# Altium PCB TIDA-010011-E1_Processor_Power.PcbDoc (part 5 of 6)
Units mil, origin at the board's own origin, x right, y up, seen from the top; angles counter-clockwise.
Board outline 4921.26 x 4921.26 mil, 4 copper layers (Top Layer, Gnd layer, Gnd/Pwr layer, Bottom Layer), stack 62.634 mil thick; 631 components, 254 nets, 1751 pads, 757 vias.
Unrouted connection lines stored in the file: 1.
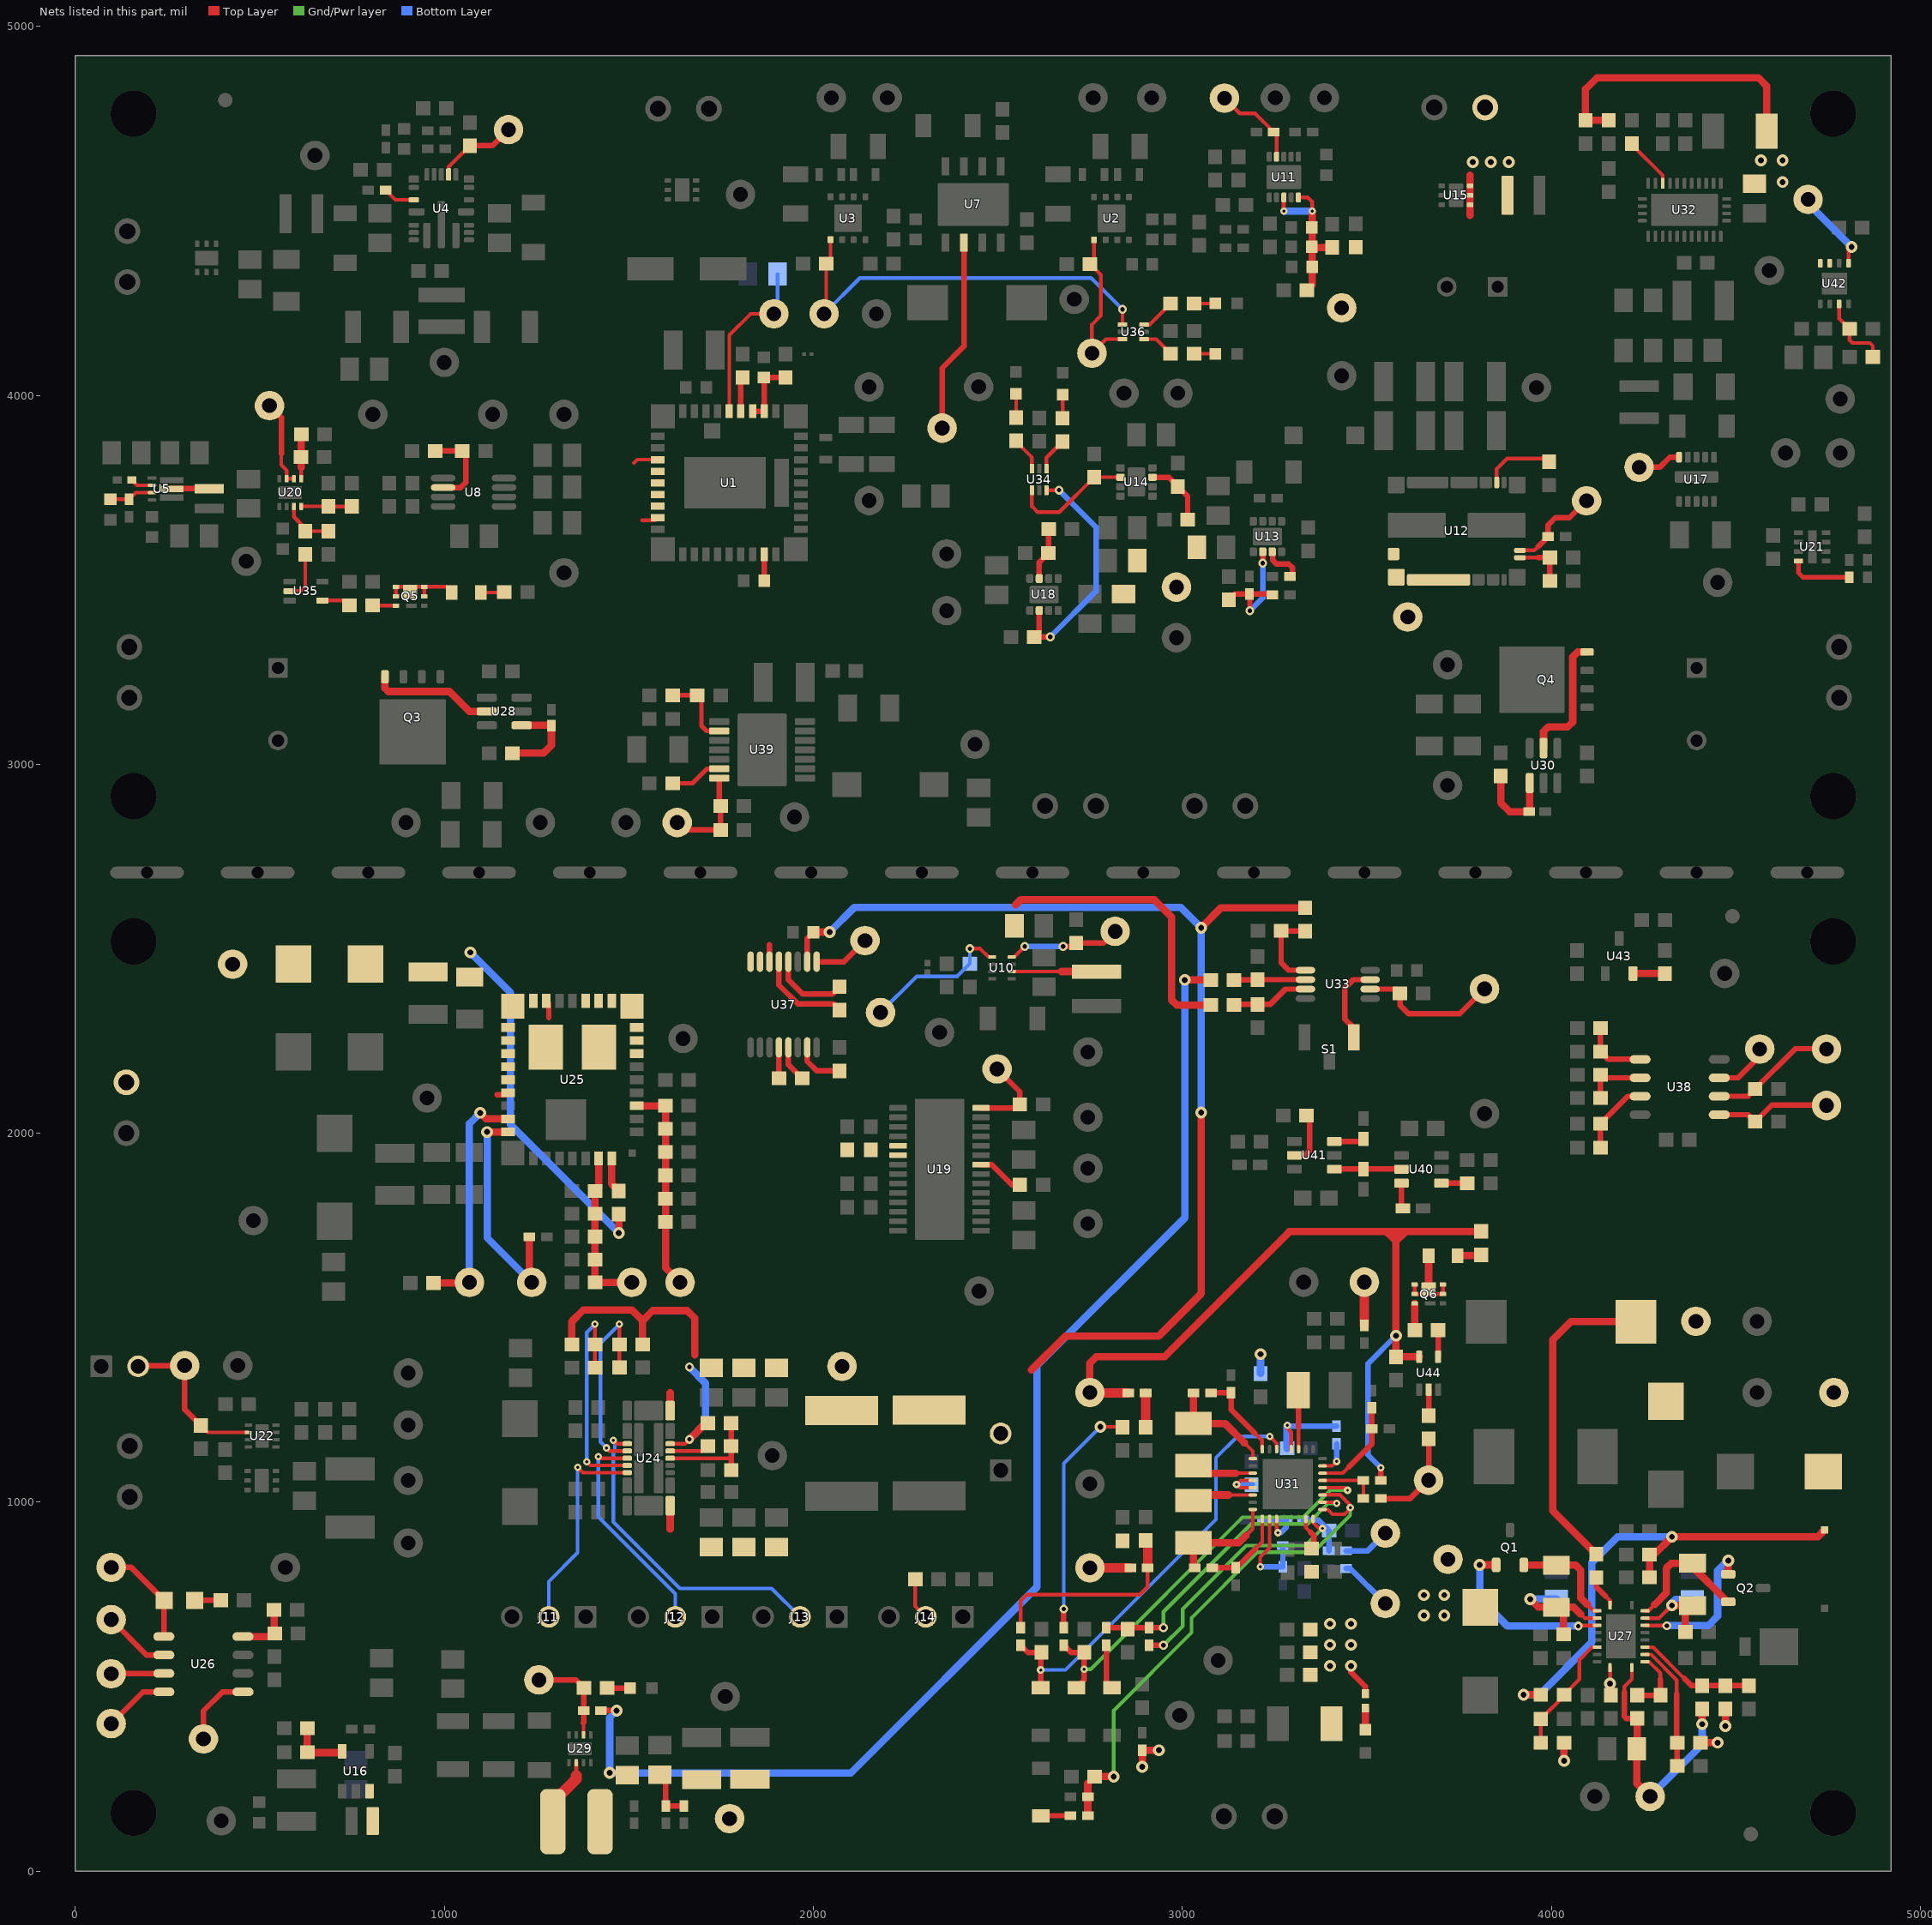
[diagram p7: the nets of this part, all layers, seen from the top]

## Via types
v1: diameter 32, hole 16, Top Layer to Bottom Layer, tented both sides, 400 vias
v2: diameter 19.68, hole 7.87, Top Layer to Bottom Layer, 176 vias
v3: diameter 24, hole 12, Top Layer to Bottom Layer, tented both sides, 112 vias
v4: diameter 20, hole 8, Top Layer to Bottom Layer, tented both sides, 35 vias
v5: diameter 17.72, hole 7.87, Top Layer to Bottom Layer, 30 vias
v6: diameter 19.68, hole 7.87, Top Layer to Bottom Layer, tented both sides, 4 vias

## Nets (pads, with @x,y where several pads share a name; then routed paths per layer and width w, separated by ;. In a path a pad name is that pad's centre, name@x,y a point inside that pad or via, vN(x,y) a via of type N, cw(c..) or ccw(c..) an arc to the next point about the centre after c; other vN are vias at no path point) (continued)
NetD3_1: D3.1 R110.2 U28.1 | length 248.8
  Top Layer w20: R110.2@1184.5,3030 1269,3030 1290,3051 D3.1@1290,3104.35 1288.75,3105.6 U28.1@1209.24,3105.6
NetD4_1: D4.1 R115.2 U30.1 | length 238
  Top Layer w20: R115.2@3863,2967.93 3863,2895.53 3887.1,2871.43 D4.1@3940.35,2871.43 3941.6,2872.68 U30.1@3941.6,2949.18
NetD5_1: D5.1 R120.1 | length 70.6
  Top Layer w15: D5.1@323.15,733.48 392.98,733.48 R120.1@393.5,734
NetD5_2: D5.2 TP63.1 U26.5 | length 279.1
  Top Layer w15: TP63.1@96.81,823 150.95,823 D5.2@240.47,733.48 239.53,732.54 U26.5@239.53,635.48
NetD6_1: D6.1 R132.2 | length 64
  Top Layer w10: R132.2@2549.54,3939.91 D6.1@2549.54,4003.88
NetD7_1: D7.1 R133.2 | length 64
  Top Layer w10: R133.2@2675.54,3937.91 D7.1@2675.54,4001.88
NetD8_1: D8.1 R134.2 | length 62
  Top Layer w15: R134.2@1441.5,496 D8.1@1503.47,496
NetD9_1: D9.1 Q5.1 Q5.2 Q5.5 Q5.6 Q5.8 | length 213.5
  Top Layer w10: Q5.2@868.61,3455.26 Q5.1@868.61,3480.85 894.2,3480.85 900.03,3475.03 905.85,3480.85 Q5.6@945.39,3480.85 ; Q5.5@945.39,3455.26 Q5.6@945.39,3480.85 ; D9.1@1019.63,3465.26 1004.04,3480.85 Q5.6@945.39,3480.85
NetD9_2: D9.2 R135.1 | length 64.5
  Top Layer w10: D9.2@1098.37,3465.26 1161.5,3465.26 R135.1@1162.5,3466.26
NetD10_1: D10.1 R140.2 | length 58.4
  Top Layer w10: R140.2@3031.5,4112.72 3088.47,4112.72 D10.1@3089.47,4111.72
NetD11_1: D11.1 R84.1 | length 80.6
  Top Layer w15: D11.1@2616.21,149.53 2616.68,150 R84.1@2696.59,150
NetD12_2: D12.2 R88.1 | length 122.1
  Top Layer w15: R88.1@2794,612.36 2794,511.47 D12.2@2809,496.47
NetD15_2: D15.2 R178.1 | length 57.8
  Top Layer w20: D15.2@3496,383.5 R178.1@3496,441.32
NetD16_1: D16.1 R142.2 | length 58.1
  Top Layer w10: R142.2@3031.5,4248.91 3089.21,4248.91 D16.1@3089.47,4249.17
NetD17_1: D17.1 Q6.1 Q6.2 Q6.5 Q6.6 Q6.8 | length 219.3
  Top Layer w10: Q6.1@3629.61,1589.59 Q6.2@3629.61,1564 Q6.5@3706.39,1564 Q6.6@3706.39,1589.59
  Top Layer w20: D17.1@3667.63,1668 3667.63,1577.17 Q6.8@3668,1576.8
NetD17_2: D17.2 R188.1 | length 64.7
  Top Layer w20: D17.2@3746.37,1668 3807.5,1668 R188.1@3810,1670.5
NetJ3_1: J3.1 L4.1 U15.4 U15.5 U15.6 | length 108
  Top Layer w20: 3780.09,4488.09 U15.4@3780.09,4516.5 U15.5@3780.09,4542.09 U15.6@3780.09,4567.68 3780.09,4596.09
  other v1: 3787,4632 3836,4632 3885,4632
NetJ6_2: J6.2 R41.1 TP24.1 U22.2 | length 443.9
  Top Layer w10: R41.1@340,1207.5 358.65,1188.84 U22.2@468.6,1188.84
  Top Layer w15: J6.2@170,1368 172,1370 TP24.1@296,1370 296,1251.5 R41.1@340,1207.5
NetJ11_2: J11.2 U24.9@1495.66,1079.55 | length 578.1
  Top Layer w10: v4(1361,1094) 1375.45,1079.55 U24.9@1495.66,1079.55
  Bottom Layer w10: J11.2@1282.73,688.92 1282.73,784.73 1361,863 v4(1361,1094)
NetJ12_2: J12.2 U24.7 | length 600.9
  Top Layer w10: v4(1417,1123) 1421.08,1118.92 U24.7@1495.66,1118.92
  Bottom Layer w10: v4(1417,1123) 1417,960 1625.73,751.27 J12.2@1625.73,688.92
NetJ13_2: J13.2 U24.5 | length 878.7
  Top Layer w10: v4(1458,1167.84) 1467.55,1158.29 U24.5@1495.66,1158.29
  Bottom Layer w10: v4(1458,1167.84) 1461.7,1164.14 1461.7,1137.6 1458,1133.9 1458,946 1638,766 1886.65,766 J13.2@1963.73,688.92
NetJ14_2: J14.2 R52.2 | length 113.8
  Top Layer w10: R52.2@2276.24,790.92 2276.24,717.42 J14.2@2304.73,688.92
NetL3_1: L3.1 U5.6 | length 102.5
  Top Layer w15: U5.6@260.72,3746.26 261.29,3746.83 L3.1@363,3746.83
NetL7_2: L7.2 L17.2 R170.1 TP12.1
NetL10_1: L10.1 U29.2 | length 186.2
  Top Layer w12: 1357.31,258 U29.2@1357.31,294
  Top Layer w30: L10.1@1294.02,134 1294.02,186.02 1357.31,249.31 1357.31,258
NetL12_1: L12.1 U31.6 | length 166.9
  Top Layer w10: 3125,1019.32 U31.6@3191,1019.32
  Top Layer w20: L12.1@3030.49,1003.93 3045.87,1019.32 3125,1019.32
NetL13_1: L13.1 U31.27 | length 160
  Top Layer w10: U31.27@3315.02,1143.33 3315.02,1205
  Top Layer w15: L13.1@3314.4,1303.11 3315.02,1302.49 3315.02,1205
NetL14_1: L14.1 U31.3 | length 169
  Top Layer w10: 3145.37,1078.37 U31.3@3191,1078.37
  Top Layer w20: L14.1@3030.49,1098.76 3050.87,1078.37 3145.37,1078.37
NetL18_1: L18.1 U10.6 | length 230.6
  Top Layer w10: U10.6@2537.57,2438.16 2672.84,2438.16
  Top Layer w20: 2672.84,2438.16 2767.5,2438.16 L18.1@2768,2437.65
NetL19_1: L19.1 U16.3
NetQ1_1: Q1.1 U27.14 | length 485.5
  Top Layer w10: v3(4073,664) 4075,664 4076.69,665.69 U27.14@4124.08,665.69
  Top Layer w20: v1(3806,830) 3806.24,829.76 Q1.1@3850.6,829.76
  Bottom Layer w20: v1(3806,830) 3806,739 3881,664 v3(4073,664)
NetQ1_2: Q1.2 R70.2 U27.12 | length 294.3
  Top Layer w10: 4098,722 4114.94,705.06 U27.12@4124.08,705.06
  Top Layer w20: Q1.2@3925.4,829.76 3926.07,829.09 R70.2@4014,829.09 4065.91,829.09 4080,815 4080,740 4098,722
NetQ2_1: Q2.1 U27.7 | length 406.2
  Top Layer w10: U27.7@4254,665.69 4312.31,665.69 v3(4313,665)
  Top Layer w20: Q2.1@4479.76,804.4 v1(4479.76,841.24)
  Bottom Layer w20: v3(4313,665) 4425,665 4450.76,690.76 4450.76,814.24 v1@4477.76,841.24
NetQ2_2: Q2.2 R76.2 U27.9 | length 365.5
  Top Layer w10: U27.9@4254,705.06 4263.13,705.06 4280.08,722
  Top Layer w20: 4280.08,722 4312.17,754.09 4312.17,821.17 4325.09,834.09 R76.2@4383,834.09 4383,824.35 Q2.2@4477.76,729.6
NetQ3_4: Q3.4 U28.5 | length 333
  Top Layer w20: Q3.4@838.91,3237.08 838.91,3206.09 848,3197 1014,3197 1068,3143 U28.5@1114.76,3143
NetQ4_4: Q4.4 U30.5 | length 355.4
  Top Layer w20: U30.5@3979,3043.67 3979,3088.53 3992,3101.53 4045,3101.53 4058,3114.53 4058,3290.53 4071.9,3304.43 Q4.4@4097.04,3304.43
NetQ5_3: Q5.3 R136.1 | length 63.4
  Top Layer w10: R136.1@805.5,3430.26 868.02,3430.26 Q5.3@868.61,3429.67
NetQ6_3: Q6.3 R189.1 | length 72.8
  Top Layer w20: Q6.3@3629.61,1538.41 3629.61,1466.89 R189.1@3630.5,1466
NetR7_1: R7.1 R11.2 U5.3 | length 120.3
  Top Layer w10: R11.2@95,3717.82 95.06,3717.88 R7.1@145,3717.88 163.54,3736.42 U5.3@207.57,3736.42
NetR8_1: R8.1 U5.2 | length 60.7
  Top Layer w10: R8.1@152.68,3770.26 166.84,3756.1 U5.2@207.57,3756.1
NetR15_1: R15.1 R16.2 U8.2 | length 229.7
  Top Layer w15: R15.1@975.5,3849.26 R16.2@1048.5,3849.26 1058,3839.76 1058,3764 1044.06,3750.06 U8.2@996.32,3750.06
NetR17_1: R17.1 U4.3 | length 87.5
  Top Layer w10: R17.1@840.36,4556.1 866.72,4529.74 U4.3@916.94,4529.74
NetR19_1: R19.1 TP51.1 U12.17 | length 254.9
  Top Layer w10: U12.17@3914.96,3579.72 3954.34,3579.72 3964.96,3590.35
  Top Layer w15: 3964.96,3590.35 R19.1@3991.71,3617.09 3991.71,3648.71 4011,3668 4049.62,3668 TP51.1@4095.71,3714.09
NetR20_2: R20.2 TP54.1 U19.28 | length 230.8
  Top Layer w15: U19.28@2454.2,2068.34 2549.84,2068.34 R20.2@2559.5,2078 2559.5,2112.5 TP54.1@2498,2174
NetR21_1: R21.1 TP10.1 U11.9 | length 241.8
  Top Layer w10: TP10.1@3114.12,4805.46 3155.58,4764 3197.2,4764 R21.1@3247.74,4713.46 3255.43,4705.77 U11.9@3255.43,4646.58
NetR25_1: R25.1 R30.2 U14.7 | length 180.3
  Top Layer w15: U14.7@2919,3777.91 2963.09,3777.91 R25.1@2988,3753.01 3014.5,3726.51 R30.2@3014.5,3663
NetR27_1: R27.1 R28.1 R31.2 U13.6 | length 346
  Top Layer w15: R27.1@3125.74,3445.5 3141.61,3461.38 R28.1@3181.74,3461.38 ; v3(3183,3416) 3183,3460.12 R28.1@3181.74,3461.38 ; v3(3217.94,3545.06) U13.6@3217.94,3575.66 ; R31.2@3244.12,3459 3241.74,3461.38 R28.1@3181.74,3461.38
  Bottom Layer w15: v3(3183,3416) 3218,3451 v3(3217.94,3545.06) v3(3217.94,3545.06)
NetR29_1: R29.1 U14.2 U34.1 | length 329.9
  Top Layer w10: U34.1@2592.31,3742.87 2592.31,3698.69 2607.7,3683.3 2666.29,3683.3 R29.1@2761,3778.01 ; R29.1@2761.09,3777.91 U14.2@2832.39,3777.91
  Top Layer w15: R29.1@2761,3778.01 R29.1@2761.09,3777.91
NetR32_1: R32.1 R33.2 U12.16 | length 144.3
  Top Layer w10: U12.16@3914.96,3560.04 3964,3560.04
  Top Layer w15: 3964,3560.04 3964.05,3560.09 R32.1@3996.21,3560.09 R33.2@3996.21,3497.09
NetR34_2: R34.2 U12.3 | length 193.5
  Top Layer w10: U12.3@3851.97,3763.98 3851.97,3800.08 3880.6,3828.7 3984.59,3828.7 R34.2@3993.71,3819.58
NetR35_1: R35.1 R37.2 U18.7 | length 144.2
  Top Layer w15: U18.7@2612.33,3503.24 2612.33,3547.34 R35.1@2637.24,3572.24 2637.24,3636.73 R37.2@2637.5,3637
NetR36_2: R36.2 U18.2 U34.3 | length 645.8
  Top Layer w10: U34.3@2631.68,3742.87 v3(2665.87,3742.87)
  Top Layer w15: U18.2@2612.33,3416.63 2612.33,3358.83 R36.2@2598.5,3345 v3(2642,3345)
  Bottom Layer w15: v3(2642,3345) 2766,3469 2766,3642.73 v3(2665.87,3742.87)
NetR38_2: R38.2 U19.22 | length 128
  Top Layer w15: U19.22@2454.2,1914.8 2483.2,1914.8 2538,1860 R38.2@2559.5,1860
NetR39_2: R39.2 U21.8 | length 174.4
  Top Layer w12: U21.8@4670,3550.82 4670,3519 4682.42,3506.58 R39.2@4807.4,3506.58
NetR45_1: R45.1 R48.2 R49.2 U24.17 | length 296.4
  Top Layer w10: U24.17@1611.8,1118.92 1777.23,1118.92
  Top Layer w15: R49.2@1777.23,1082.92 1777.23,1118.92 R48.2@1777.23,1151.92 R45.1@1777.23,1213.92
NetR46_1: R46.1 R50.2 U24.6 | length 539.6
  Top Layer w10: v4(1439,1147) 1447.39,1138.61 U24.6@1495.66,1138.61 ; R50.2@1474.24,1364.92 R46.1@1474.24,1426.92 v4@1474.24,1481.71
  Bottom Layer w10: v4(1439,1147) 1423,1163 1423,1430.93 v4(1474.01,1481.93)
NetR47_1: R47.1 R51.2 U24.8@1495.66,1099.24 | length 613.1
  Top Layer w10: v4(1386,1109) 1395.76,1099.24 U24.8@1495.66,1099.24 ; v4(1408,1482) 1408.23,1481.77 R47.1@1408.23,1426.99 R51.2@1408.23,1364.86
  Bottom Layer w10: v4(1386,1109) 1386,1460 v4(1408,1482)
NetR48_1: R48.1 U24.18@1611.8,1138.61 | length 107.9
  Top Layer w10: U24.18@1611.8,1138.61 1700.92,1138.61 R48.1@1714.24,1151.92
NetR54_2: R54.2 TP30.1 U25.28 | length 640.5
  Top Layer w20: v1(1115.81,2003.19) U25.28@1172.95,2003.19 ; R54.2@1230.48,1718.51 1230.48,1601.75 TP30.1@1236.72,1595.51
  Bottom Layer w20: v1(1115.81,2003.19) 1115.81,1716.42 TP30.1@1236.72,1595.51
NetR55_1: R55.1 U25.36 | length 96.3
  Top Layer w20: U25.36@1453.46,1931.34 1453.46,1862.26 R55.1@1472.72,1843
NetR56_2: R56.2 TP34.1 U25.27 | length 652.2
  Top Layer w20: R56.2@970.5,1594 1066.22,1594 TP34.1@1067.72,1595.51 ; v1(1097,2055) 1113.37,2038.63 U25.27@1172.95,2038.63
  Bottom Layer w20: TP34.1@1067.72,1595.51 1067.72,2025.72 v1(1097,2055)
NetR57_2: R57.2 R58.2 R59.2 R60.2 R61.2 TP32.1 U25.35 | length 439.4
  Top Layer w20: U25.35@1418.03,1931.34 1418.03,1853.32 R57.2@1408.22,1843.51 R58.2@1408.22,1781.51 R59.2@1408.22,1719.51 R60.2@1408.22,1657.51 R61.2@1408.22,1595.51 TP32.1@1507.72,1595.51
NetR62_2: R62.2 R63.2 R64.2 R65.2 R66.2 R67.2 TP33.1 U25.4 | length 572.8
  Top Layer w20: U25.4@1521.38,2074.06 R67.2@1599.23,2074.05 R66.2@1599.23,2011.51 R65.2@1599.23,1948.51 R64.2@1599.23,1885.51 R63.2@1599.23,1822.51 R62.2@1599.23,1759.51 1599.23,1635 TP33.1@1638.72,1595.51
NetR71_2: R71.2 U27.11 | length 90.2
  Top Layer w10: 4147,745 4159.51,732.49 U27.11@4159.51,720.8
  Top Layer w15: R71.2@4122,795.5 4122,770 4147,745
NetR72_1: R72.1 R73.2 R74.1 U27.17 | length 329.8
  Top Layer w10: R72.1@3971.5,348 R74.1@3971.5,412 4034.5,474.99 R73.2@4034.5,478 4076,519.5 4076,572.2 4110.43,606.63 U27.17@4124.08,606.63
NetR75_1: R75.1 R103.1 U27.3 | length 348.2
  Top Layer w10: U27.3@4254,586.94 4270.46,586.94 4340,517.4 4340,480
  Top Layer w15: 4340,480 4340,349.5 R75.1@4341.5,348 4341.5,286 R103.1@4342.5,285
NetR78_1: R78.1 R79.2 U31.9 | length 226.9
  Top Layer w10: 3200.3,875.7 3216.59,892 U31.9@3216.59,954.35
  Top Layer w15: R78.1@3081.11,821.84 3146.43,821.84 3200.3,875.7
NetR82_1: R82.1 R86.2 U31.22 | length 264.7
  Top Layer w10: U31.22@3379.98,1078.37 3434.37,1078.37 3451.5,1095.5
  Top Layer w15: 3451.5,1095.5 3514,1158 R86.2@3514,1198.62 3514,1254.97 R82.1@3513.49,1255.49
NetR90_1: R90.1 R92.2 U31.32 | length 242.1
  Top Layer w10: 3196.5,1186.5 3214.3,1168.7 3214.3,1168.6 3216.3,1166.6 3216.3,1143.62 U31.32@3216.59,1143.33
  Top Layer w15: R90.1@3077.62,1296 R92.2@3131.62,1296 ; R92.2@3132,1296.38 3132,1251 3196.5,1186.5
NetR93_2: R93.2 U31.23 | length 91.3
  Top Layer w10: U31.23@3379.98,1098.06 3406.06,1098.06 v4(3418,1110)
  Bottom Layer w15: v4(3418,1110) R93.2@3418,1158.38
NetR96_1: R96.1 R97.2 U31.11 | length 149.7
  Top Layer w10: U31.11@3255.96,954.35 3255.96,920.04 v4(3259,917)
  Bottom Layer w15: R97.2@3218.11,950.84 3218.61,951.34 R96.1@3280.87,951.34 3280.87,930.87 3267,917 v4(3259,917)
NetR99_1: R99.1 R100.2 U31.10 | length 259.2
  Top Layer w10: v4(3211,825) 3211,850.49 3236.28,875.77 U31.10@3236.28,954.35
  Bottom Layer w15: v4(3211,825) 3271.95,825 R100.2@3272.49,824.46 3272.49,881.22 R99.1@3271.87,881.84
NetR101_1: R101.1 R102.1 U31.21 | length 160
  Top Layer w10: U31.21@3379.98,1058.69 3490.71,1058.69 R101.1@3490.87,1058.84 R102.1@3490.87,1009.84
NetR104_1: R104.1 R105.2 R106.1 U27.4 | length 325.1
  Top Layer w10: U27.4@4254,606.63 4275.8,606.63 4360.22,522.22
  Top Layer w15: 4360.22,522.22 4379.94,502.5 R105.2@4409,502.5 R104.1@4472,502.5 R106.1@4536,502.5
NetR109_1: R109.1 R111.2 U27.2 | length 177.7
  Top Layer w10: U27.2@4254,567.26 4265.11,567.26 4296,536.37 4296,520
  Top Layer w15: R109.1@4233,476.5 R111.2@4296,476.5 4296,520
NetR112_1: R112.1 R116.2 U20.5 | length 119
  Top Layer w10: U20.5@611.81,3773.66 611.81,3804
  Top Layer w20: 611.5,3804.31 R116.2@611.5,3832.26 R112.1@611.5,3893
NetR114_2: R114.2 R117.2 U20.4 | length 137.2
  Top Layer w10: U20.4@611.81,3698.86 685.91,3698.86 R117.2@686,3698.76 R114.2@749,3698.76
NetR119_1: R119.1 R121.2 U26.4 | length 149.9
  Top Layer w20: U26.4@454.09,635.48 527.61,635.48 538.31,646.19 R119.1@538.31,707.48
NetR123_2: R123.2 U32.9 | length 142.5
  Top Layer w10: R123.2@4218,4682.5 4218,4680 4301.86,4596.14 U32.9@4301.86,4574.69
NetR125_1: R125.1 R126.2 U33.3 | length 211.8
  Top Layer w15: R125.1@3139.8,2347.31 3141.3,2348.8 R126.2@3204.37,2348.8 3237.8,2348.8 3279.51,2390.51 U33.3@3333.71,2390.51
NetR127_2: R127.2 TP70.1 U33.6 | length 384.2
  Top Layer w15: U33.6@3508.9,2390.51 3578.6,2390.51 R127.2@3589.81,2379.31 3589.81,2347.19 3613,2324 3752,2324 TP70.1@3819,2391
NetR128_1: R128.1 R129.2 U33.2 | length 194.2
  Top Layer w15: R128.1@3139.8,2415.31 3140.3,2415.81 R129.2@3204.3,2415.81 3204.59,2416.1 U33.2@3333.71,2416.1
NetR130_1: R130.1 R131.2 U33.1 | length 226.2
  Top Layer w15: R130.1@3333.3,2547.81 3332.81,2548.31 R131.2@3267.8,2548.31 3267.8,2462.2 3288.31,2441.69 U33.1@3333.71,2441.69
NetR132_1: R132.1 U34.6 | length 93.5
  Top Layer w10: R132.1@2549.54,3876.91 2549.54,3874.55 2592.31,3831.77 U34.6@2592.31,3801.13
NetR133_1: R133.1 U34.4 | length 91.9
  Top Layer w10: U34.4@2631.68,3801.13 2631.68,3831.06 R133.1@2675.54,3874.91
NetR136_2: R136.2 U35.4 | length 78.8
  Top Layer w10: U35.4@669.29,3443.67 729.09,3443.67 R136.2@742.5,3430.26
NetR137_1: R137.1 R138.2 U20.3 | length 142.9
  Top Layer w10: U20.3@592.13,3698.86 592.13,3670.43 623,3639.56 R137.1@623,3631.76 R138.2@686,3631.76
NetR137_2: R137.2 U35.2 | length 134.3
  Top Layer w10: U35.2@580.71,3469.26 610.26,3469.26 623,3482 R137.2@623,3568.76
NetR139_1: R139.1 TP49.1 U2.1 U36.3 | length 432.9
  Top Layer w10: U2.1@2760.76,4421.43 2760.76,4367.27 R139.1@2749.5,4356 2779,4326.5 2779,4216 2755,4192 TP49.1@2755,4114 2793.03,4152.03 U36.3@2837.87,4152.03
NetR140_1: R140.1 U36.4 | length 88.7
  Top Layer w10: U36.4@2896.13,4152.03 2929.19,4152.03 R140.1@2968.5,4112.72
NetR141_1: R141.1 TP50.1 U3.1 U36.1 | length 1133.9
  Top Layer w10: TP50.1@2029,4221 2035,4227 R141.1@2035,4357.06 2046.5,4368.56 U3.1@2046.5,4421.86 ; U36.1@2837.87,4191.4 v3(2837.87,4232.87)
  Bottom Layer w10: TP50.1@2029,4221 2126,4318 2752.73,4318 v3(2837.87,4232.87)
NetR142_1: R142.1 U36.6 | length 96.2
  Top Layer w10: U36.6@2896.13,4191.4 2910.99,4191.4 R142.1@2968.5,4248.91
NetR143_1: R143.1 U37.13 | length 255.8
  Top Layer w15: U37.13@1906.64,2464.76 1906.64,2401.6 1957.47,2350.78 2054.43,2350.78 R143.1@2071.23,2333.98
NetR143_2: R143.2 U37.12 | length 212.4
  Top Layer w15: U37.12@1932.23,2464.76 1932.23,2416.01 1971.47,2376.78 2051.04,2376.78 R143.2@2071.23,2396.97
NetR144_1: R144.1 U37.4 | length 84
  Top Layer w15: U37.4@1906.64,2232.47 1906.64,2148.57 R144.1@1906.74,2148.47
NetR144_2: R144.2 U37.5 | length 99.5
  Top Layer w15: U37.5@1932.23,2232.47 1932.23,2185.97 R144.2@1969.73,2148.47
NetR145_1: R145.1 U37.7 | length 136.3
  Top Layer w15: U37.7@1983.41,2232.47 1983.41,2194.67 2009.11,2168.98 R145.1@2071.23,2168.98
NetR146_1: R146.1 R151.1 U38.7 | length 202.9
  Top Layer w15: R151.1@4133.5,1961 R146.1@4133.5,2026 4207.5,2100 U38.7@4240.72,2100
NetR147_1: R147.1 R152.1 U38.6 | length 173.5
  Top Layer w15: R147.1@4133.5,2095 R152.1@4133.5,2158 4141.5,2150 U38.6@4240.72,2150
NetR148_1: R148.1 R153.1 U38.5 | length 179.9
  Top Layer w15: R148.1@4133.5,2285 R153.1@4133.5,2221 4154.5,2200 U38.5@4240.72,2200
NetR149_1: R149.1 TP89.1 U38.2 | length 344.6
  Top Layer w15: U38.2@4455.28,2100 4532.5,2100 R149.1@4552.5,2120 4661.5,2229 4745,2229 TP89.1@4746,2228
NetR150_1: R150.1 TP88.1 U38.1 | length 318.7
  Top Layer w15: U38.1@4455.28,2050 4533.5,2050 R150.1@4552.5,2031 4597.5,2076 4739,2076 TP88.1@4745,2082
NetR155_2: R155.2 R156.1 U39.2 | length 208.4
  Top Layer w12: R155.2@1618.5,3187 R156.1@1685.5,3187 1697,3175.5 1697,3104 1710.82,3090.18 U39.2@1744.86,3090.18
NetR157_2: R157.2 U39.6 | length 142.9
  Top Layer w12: R157.2@1618.5,2948 1672,2948 1711.82,2987.82 U39.6@1744.86,2987.82
NetR158_1: R158.1 R159.2 TP94.1 U39.7 | length 267.5
  Top Layer w15: TP94.1@1631,2842 1651,2822 R158.1@1748.5,2822 R159.2@1748.5,2887 1744.86,2890.65 U39.7@1744.86,2962.23
NetR160_1: R160.1 U40.6 | length 70.1
  Top Layer w15: U40.6@3593.87,1864.6 3593.87,1799.57 R160.1@3597.44,1796
NetR161_1: R161.1 U40.1 | length 70.6
  Top Layer w15: U40.1@3702.13,1864.6 3771.91,1864.6 R161.1@3772.5,1864
NetR162_1: R162.1 U40.5 U41.1 | length 182
  Top Layer w15: U41.1@3412.13,1902.6 3490.96,1902.6 R162.1@3491,1902.56 3593.31,1902.56 U40.5@3593.87,1902
NetR163_1: R163.1 U41.3 | length 81.8
  Top Layer w15: U41.3@3412.13,1977.4 3483.96,1977.4 R163.1@3491,1984.44
NetR165_2: R165.2 U41.5 | length 145
  Top Layer w15: U41.5@3303.87,1940 3332,1940 3345,1953 3345,2039.5 R165.2@3336.5,2048
NetR168_1: R168.1 R169.2 U42.3 | length 209.1
  Top Layer w10: U42.3@4780.35,4247.8 4780.35,4208.16 R169.2@4808.5,4180 4808.5,4149.5 4816.25,4141.75 4863.25,4141.75 4871.5,4133.5 R168.1@4871.5,4104
NetR172_2: R172.2 TP103.1 U10.1 | length 407.1
  Top Layer w10: v3(2424,2500) 2452,2500 2474.47,2477.53 U10.1@2484.43,2477.53
  Bottom Layer w10: TP103.1@2182,2327 2280,2425 2389.5,2425 R172.2@2424,2459.5 v3(2424,2500)
NetR173_2: R173.2 TP105.1 U10.8 | length 309.2
  Top Layer w10: U10.8@2537.57,2477.53 2544.53,2477.53 v3(2573,2506)
  Top Layer w15: v3(2677,2506) 2702.5,2506 R173.2@2712,2515.5 2786.5,2515.5 TP105.1@2818,2547
  Bottom Layer w15: v3(2573,2506) v3(2677,2506)
NetR184_1: R184.1 R185.2 U16.5 | length 160.4
  Top Layer w20: R184.1@628.47,387.53 R185.2@628.47,321.53 629.27,320.72 U16.5@722.57,320.72
NetR186_2: R186.2 U43.2 | length 86.7
  Top Layer w20: U43.2@4221.4,2432.76 4307.75,2432.76 R186.2@4308,2432.5
NetR187_2: R187.2 TP48.1 U1.26 | length 463.6
  Top Layer w10: U1.26@1772.01,3956.57 1772.39,3956.94 1772.39,4163.39 1830,4221 TP48.1@1893,4221
  Bottom Layer w10: TP48.1@1893,4221 1903,4231 R187.2@1903,4329
NetR189_2: R189.2 U44.4 | length 72.5
  Top Layer w15: U44.4@3693.18,1393.58 3693.5,1393.9 R189.2@3693.5,1466
NetR190_2: R190.2 U44.2 | length 71.2
  Top Layer w15: U44.2@3667.59,1305 3668,1304.59 R190.2@3668,1234
NetRES1_2: RES1.2 TP47.1 U4.19 | length 224.7
  Top Layer w10: U4.19@1011.43,4598.64 1011.43,4619.29 RES1.2@1068.74,4676.61
  Top Layer w15: RES1.2@1068.74,4676.61 1130.24,4676.61 TP47.1@1173.74,4720.1
NetS1_1: S1.1 U33.7 | length 221.6
  Top Layer w15: S1.1@3465.23,2260.31 3465.23,2284.77 3440,2310 3440,2393 3463.1,2416.1 U33.7@3508.9,2416.1
NetTP16_1: TP16.1 U12.9 U12.10 U12.11
NetTP62_1: TP62.1 U17.5 | length 119.7
  Top Layer w15: TP62.1@4238,3805 4294,3805 4321.26,3832.26 U17.5@4346.38,3832.26
NetTP64_1: TP64.1 U26.7 | length 143.1
  Top Layer w15: TP64.1@96.81,534.48 97.81,535.48 U26.7@239.53,535.48
NetTP65_1: TP65.1 U26.1 | length 206.8
  Top Layer w15: TP65.1@347,358 347,434 398.48,485.48 U26.1@454.09,485.48 U26.1@454.09,483.1
NetTP66_1: TP66.1 U26.6 | length 182.5
  Top Layer w15: TP66.1@96.81,681.48 192.81,585.48 U26.6@239.53,585.48
NetTP67_1: TP67.1 U26.8 | length 178.3
  Top Layer w15: TP67.1@96.81,399.48 182.81,485.48 U26.8@239.53,485.48
NetTP90_1: TP90.1 U38.3 | length 153.2
  Top Layer w15: U38.3@4455.28,2150 4506,2150 4565,2209 TP90.1@4565,2228
NetTP98_1: TP98.1 U20.6 U20.7 | length 240.1
  Top Layer w10: TP98.1@526.31,3976.3 TP98.1@528.31,3974.31 ; 558,3841 558,3811 572.44,3796.56 U20.7@572.44,3773.66 U20.6@592.13,3773.66
  Top Layer w15: TP98.1@526,3972 558,3940 558,3841
NetTP100_1: TP100.1 U7.2 | length 527.4
  Top Layer w15: TP100.1@2349,3911 2349,4074 2408,4133 U7.2@2408,4414
NetTP108_1: TP108.1 U37.9 | length 154.7
  Top Layer w15: U37.9@2009,2464.76 2082.76,2464.76 TP108.1@2140,2522
NetU25_17: U25.17 U25.18 U25.19 U25.20 U25.21 U25.22 U25.23 U25.24 U25.25 U25.39 | length 81.1
  Top Layer w15: 1142.38,2104 1167.46,2104 U25.25@1172.95,2109.49 ; U25.17@1276.3,2358.51 1283,2351.81 1283,2313
PG_1OR2A: R113.2 R134.1 TP71.1 U29.6 | length 259.4
  Top Layer w10: U29.6@1377,368.8 1377,402 ; R134.1@1377.38,494.87 R134.1@1378.5,496
  Top Layer w15: TP71.1@1256,518 1356.5,518 R134.1@1378.5,496 ; 1377,402 1377.38,402.38 R113.2@1377.38,435 R134.1@1377.38,494.87
PG_3P3V: R26.1 U13.7 | length 112.1
  Top Layer w15: U13.7@3243.54,3575.66 3245.14,3574.05 3245.14,3552.86 3255,3543 3288,3543 3299,3532 3299,3516.64 R26.1@3291.36,3509
PH: U1.34 U1.35 U1.36 U1.37 U1.38 U1.39 | length 113.2
  Top Layer w10: 1513.67,3816.67 1522.66,3825.66 U1.34@1578.12,3825.66 ; 1535.81,3661.53 1571.46,3661.53 U1.39@1578.12,3668.18
PM_2.5V_OUT: C105.1 C106.1 C107.1 C108.1 J16.1 R55.2 R125.2 R171.1 TP29.1 U25.8 U25.9 U25.10 U25.11 U25.12 U25.13 U25.14 U25.38 U37.14 U37.15 U37.16 | length 1808.6
  Top Layer w15: U37.14@1881.05,2464.76 1881.05,2510.36
  Top Layer w20: v1(1472.72,1729.28) R55.2@1472.72,1780.01 ; 2548,2619 2562,2633 2924,2633 2971,2586 2971,2361 2984.69,2347.31 R125.2@3076.81,2347.31
  Bottom Layer w20: v1(1070,2490) 1179,2381 1179,2023 v1(1472.72,1729.28)
PM_3.6V_OUT: C92.1 C93.1 C94.1 C95.1 C96.1 C97.1 C98.1 C99.1 C112.1 C113.1 C159.1 J10.2 R45.2 R46.2 R47.2 R130.2 TP52.1 U19.5 U19.6 U24.1@1611.8,1247.86 U24.13 U24.19@1611.8,1158.29 U37.10 | length 4105.9
  Top Layer w10: U24.19@1611.8,1158.29 1652.29,1158.29 v3(1664,1170)
  Top Layer w15: U37.10@1983.41,2464.76 1983.41,2528.17 C159.1@2000.02,2544.78
  Top Layer w20: R47.2@1345.24,1426.99 1345.24,1489.24 1377,1521 1508,1521 1537.23,1491.77 ; R46.2@1537.23,1426.92 1537.23,1491.77 ; 1611.8,926.8 U24.13@1611.8,989.98 ; U24.1@1611.8,1247.86 1611.8,1296.8 ; v3(1664,1170) 1707.92,1213.92 R45.2@1714.24,1213.92 ; 1679,1399 1679,1498 1658,1519 1564.46,1519 1537.23,1491.77 ; C159.1@2000.02,2544.78 2000.25,2545 v1(2044,2545) ; 2591,1358 2683,1450 2936,1450 3051,1565 v1(3051,2056) ; v1(3051,2557) 3104.8,2610.8 R130.2@3333.3,2610.8
  Bottom Layer w20: v3(1664,1170) 1707.92,1213.92 1707.92,1322.08 v3(1664,1366) ; v1(2044,2545) 2111,2612 2996,2612 v1(3051,2557) v1(3051,2056)
PMIC_1V1: R77.2 TP81.1 | length 109.4
  Top Layer w25: TP81.1@2749.49,821.84 R77.2@2858.87,821.84
PMIC_1V1_EN: C70.1 C71.1 L12.2 R77.1 R78.2 R95.2 U31.8 | length 857.9
  Top Layer w10: R95.2@2562,659.6 2562,732 2579,749 2884,749 2906.11,771.11 R77.1@2906.11,821.84 ; 3172.5,909.5 3191,928 U31.8@3191,979.94
  Top Layer w20: R78.2@3033.87,821.84 3030.49,825.22 L12.2@3030.49,889.76 3152.76,889.76 3172.5,909.5
  Top Layer w25: C70.1@2900.49,896.35 2906.11,890.72 R77.1@2906.11,821.84
PMIC_1V5: R81.2 TP82.1 | length 117.4
  Top Layer w25: R81.2@3493.49,1478.73 TP82.1@3493.49,1596.11
PMIC_1V8_1: R94.2 TP84.1 | length 126.2
  Bottom Layer w15: R94.2@3444.11,868 3502.65,868 TP84.1@3550.49,915.84
PMIC_1V8_1_EN: C84.1 R87.2 R94.1 R96.2 U31.16 | length 805.5
  Top Layer w10: U31.16@3354.39,954.35 3354.39,944.61 3371,928 3371.64,928.64 v4(3379.64,928.64)
  Top Layer w15: R87.2@2910,612.36 2910.36,612 v3(2949,612)
  Gnd/Pwr layer w10: v3(2949,612) 3001,664 3001,710 3173,882 3333,882 v4(3379.64,928.64)
  Bottom Layer w15: R96.2@3328.11,951.34 3369.16,951.34 C84.1@3397.5,923 ; R94.1@3396.87,868 C84.1@3396.87,922.36
PMIC_1V8_2: R98.2 TP85.1 | length 145.2
  Bottom Layer w15: R98.2@3444.11,819.84 3455.16,819.84 TP85.1@3550,725
PMIC_3V3: C193.1 R89.2 R101.2 R188.2 TP83.1 U44.5 | length 2308.3
  Top Layer w15: R101.2@3538.11,1058.84 v4(3538.11,1092.89)
  Top Layer w20: TP83.1@2749,1297 2749,1376 2767,1394 2952,1394 3289.5,1731.5 3289.5,1733.5 R188.2@3810,1733.5 ; 3557,1733.5 3557,1729 3579,1707 3605.5,1733.5 ; 3579,1733.5 v1(3579,1451) C193.1@3579,1393.5 3579.09,1393.58 U44.5@3642,1393.58
  Top Layer w25: TP83.1@2750,1296 R89.2@2853.38,1296
  Top Layer w30: TP83.1@2749,1297 TP83.1@2750,1296
  Bottom Layer w15: v4(3538.11,1092.89) 3503,1128 3503,1375 v1(3579,1451)
PMIC_3V3_EN: C80.1 C81.1 L14.2 R89.1 R90.2 R91.2 U31.1 | length 1032.7
  Top Layer w10: v1(2778,1204) 2836.76,1204 C81.1@2837.42,1203.34 ; 3168,1161 3191,1138 U31.1@3191,1117.74
  Top Layer w15: R91.2@2678.58,659.6 v3(2678.58,710.11)
  Top Layer w20: R90.2@3030.38,1296 3030.49,1295.89 L14.2@3030.49,1212.93 3116.07,1212.93 3168,1161
  Top Layer w25: C80.1@2900.42,1203.34 R89.1@2900.42,1295.8
  Bottom Layer w10: v3(2678.58,710.11) 2678.58,1104.58 v1(2778,1204)
PMIC_IN: C73.1 C78.1 C82.1 C86.1 C114.1 C115.1 C116.1 C117.1 C118.1 C122.1 C179.1 C180.1 C181.1 L11.2 R70.1 R72.2 R75.2 R76.1 R80.1 R83.2 R93.1 R104.2 R178.2 TP87.1 U27.8 U27.13 U27.20 U31.4 U31.5 U31.15 U31.28 | length 1573.7
  Top Layer w10: U31.5@3191,1039 3156,1039 v4(3147,1048) 3148,1048 3158.69,1058.69 U31.4@3191,1058.69 ; v4(3285,1208) 3285,1200 3295.33,1189.67 U31.28@3295.33,1143.33 ; U31.15@3334.7,954.35 3334.7,930.94 3347,918.64 ; 4079,697 4090.63,685.37 U27.13@4124.08,685.37 ; v1@4159.51,514.51 U27.20@4159.51,551.51 ; U27.8@4254,685.37 4292.37,685.37 v1(4327,720)
  Top Layer w15: C86.1@3346.98,871 3357,881.02 3357,908.64 3347,918.64 ; v1(3457,556) 3457,539 3496,500 R178.2@3496,480.69 ; v1@4159.51,514.51 4159.51,477.99 C118.1@4161,476.5
  Top Layer w20: v1(2891.53,282.29) R83.2@2891.53,327.38 v1(2936.62,327.38) ; v1(3943,737) 3965.09,714.91 R70.1@4014,714.91 ; C117.1@4033.5,642 4033.5,695.42 R70.1@4014,714.91 ; v1(4034.5,298.5) R72.2@4034.5,348 ; 4079,697 4061.09,714.91 R70.1@4014,714.91 ; v1(4327,720) 4367.91,720 4368,719.91 4363.5,715.42 C116.1@4363.5,648 ; R75.2@4404.5,348 v1(4451,348) ; v1(4472,393) R104.2@4472,439.5
  Bottom Layer w15: v4(3285,1208) 3287.38,1205.62 R93.1@3418,1205.62
  Bottom Layer w20: v4(3147,1048) 3186.83,1048 C82.1@3187.49,1047.35 ; R80.1@3212,1348.5 v1(3212,1401) ; C78.1@3283.99,1145.84 3283.99,1206.99 v4(3285,1208) ; v1(3943,737) C114.1@4014,737 ; v1(4327,720) 4327,726.83 4336.17,736 C122.1@4382,736
  other v1: 4159,508 3400,556 3400,613 3457,613 3400,670 3457,670 3655,693 3710,693 3655,748 3710,748
PMIC_PWRFAIL_SNS: C85.1 D14.2 R95.1 U31.30 | length 1184.6
  Top Layer w10: v4(3237,1178) 3255.96,1159.04 U31.30@3255.96,1143.33
  Top Layer w15: R95.1@2562,612.36 2581.86,592.5 C85.1@2618,592.5 2616,590.5 v4(2616,545) D14.2@2616,496.47
  Bottom Layer w10: v4(2616,545) 2683,545 3091,953 3091,1120 3149,1178 v4(3237,1178)
PMIC_RESETOUTn: R102.2 R190.1 TP97.1 | length 261.7
  Top Layer w15: R102.2@3538.11,1009.84 3617.81,1009.84 TP97.1@3667.39,1059.42 3668,1060.03 R190.1@3668,1171.01
PMIC_V1V1EN: C83.1 D13.2 R91.1 U31.20 | length 1153.9
  Top Layer w10: U31.20@3379.98,1039 3441,1039 v4(3448,1032)
  Top Layer w15: R91.1@2678.58,612.36 2698.43,592.5 C83.1@2734,592.5 v4(2734,547) 2734,517.56 D13.2@2713.11,496.68
  Gnd/Pwr layer w10: v4(2734,547) 2751.5,547 3163.2,958.7 3327.7,958.7 3401,1032 v4(3448,1032)
PMIC_V1V8EN: C77.1 R84.2 R85.2 U31.17 U31.19 | length 1431.9
  Top Layer w10: U31.17@3379.98,979.94 3394.06,979.94 3407,967 3440,967 3455,982 v4(3455,985) 3455,992.1 3427.59,1019.51 3380.18,1019.51 U31.19@3379.98,1019.32
  Top Layer w20: R84.2@2743.83,150 R85.2@2743.83,201 2743.83,237.34 C77.1@2762.5,256 v1(2814,256)
  Gnd/Pwr layer w10: v1(2814,256) 2814,435 3025,646 3025,686 3203,864 3355,864 3455,964 v4(3455,985)
PMIC_V3V3EN: C79.1 R87.1 R88.2 U31.18 | length 828.4
  Top Layer w10: U31.18@3379.98,999.63 3415.37,999.63 v4(3418.19,996.82)
  Top Layer w15: R88.2@2794,659.6 R87.1@2910,659.6 v3(2948.64,659.6)
  Gnd/Pwr layer w10: v3(2948.64,659.6) 2948.64,702.64 3187,941 3340,941 3395.81,996.82 v4(3418.19,996.82)
RT: R3.2 U1.9 | length 71
  Top Layer w15: U1.9@1866.5,3568.77 1866.57,3568.7 R3.2@1866.57,3497.77
SS: C111.1 U1.25 | length 93.6
  Top Layer w15: U1.25@1803.51,3956.57 1803.51,4043.77 C111.1@1808.01,4048.27
SVC_5V: C153.1 C154.1 L15.2 R122.2 TP68.1 U42.5 U42.7 U42.8 | length 1019.4
  Top Layer w10: U42.5@4805.94,4358.04 4805.94,4393.94 v1(4814,4402)
  Top Layer w20: R122.2@4155.74,4745.5 C154.1@4092.74,4745.5 4092.74,4829.74 4124,4861 4561,4861 4583.83,4838.17 L15.2@4583.83,4716
  Bottom Layer w10: v1@4806,4400 4809,4397 v1(4814,4402)
  Bottom Layer w20: TP68.1@4696,4531 4696,4520 v1(4814,4402)
  other v1: 4627,4578 4568,4637 4627,4637
VADJ: R4.2 R18.2 U1.23 U1.24 | length 181.4
  Top Layer w15: U1.24@1835.01,3956.57 U1.23@1866.5,3956.57 1866.5,4047.72 R4.2@1866.01,4048.21 1923.95,4048.21 R18.2@1924.01,4048.27
VCC_1.8V_2A: C134.1 C135.1 C136.1 C137.1 C138.1 L10.2 R68.2 R113.1 R128.2 TP55.1 | length 3607.4
  Top Layer w15: R113.1@1424.62,435 v1(1467,435) ; C135.1@1584,261 1600,245 R68.2@1600,176.62 C138.1@1649,176.62
  Top Layer w20: v1(3006.69,2415.31) R128.2@3076.81,2415.31
  Bottom Layer w20: v1(1467,435) 1448,416 v1(1448,266) 2102,266 2606,770 2606,1370 3006.69,1770.69 v1(3006.69,2415.31)
VOUT1: C120.1 L8.2 R71.1 TP36.1 | length 876.4
  Top Layer w20: R71.1@4122,858.5 4004,976.5 4004,1440 4053,1489 L8.2@4229.76,1489
VOUT2: C124.1 C125.1 L9.2 R73.1 R107.2 TP38.1 | length 1316.3
  Top Layer w20: v1(3925,478) R73.1@3971.5,478 ; R107.2@4266.5,796 C125.1@4266.5,858 4279,858 v1(4327,906) 4722.7,906 L9.2@4741,924.3
  Bottom Layer w20: v1(3925,478) 3968,478 4110,620 4110,836 4180,906 v1(4327,906)
VOUT3: C126.1 R105.1 R109.2 TP40.1 U27.1 | length 701.2
  Top Layer w10: 4198,485 4198,499.57 4218.56,520.13 U27.1@4218.56,551.51
  Top Layer w15: 4198,485 4198,418.8 4203.3,413.5 R109.2@4233,413.5
  Top Layer w20: R109.2@4233,413.5 4233,332 C126.1@4232,331 4232,238 TP40.1@4268,202 ; v1(4409,398) R105.1@4409,439.5
  Bottom Layer w20: TP40.1@4268,202 4409,343 v1(4409,398)
VTT_DDR: C34.1 C35.1 C36.1 C37.1 C38.1 C39.1 TP80.1 U11.3 U11.5 | length 460
  Top Layer w10: U11.5@3314.49,4536.35 3339.91,4536.35 3351.88,4524.37 v4(3351.88,4498.88)
  Top Layer w12: v4(3275.12,4498.88) U11.3@3275.12,4536.35
  Top Layer w20: C34.1@3337.5,4285 3351.76,4299.26 C37.1@3351.76,4347.8 3351.88,4347.92 C38.1@3351.88,4401.67 ; C39.1@3350.56,4463 C39.1@3351.88,4464.32 ; C38.1@3350.76,4402.8 C38.1@3351.88,4401.67 ; v4(3351.88,4498.88) C39.1@3351.88,4464.32 ; C36.1@3406,4400.5 3353.05,4400.5 C38.1@3351.88,4401.67 ; C38.1@3351.88,4401.67 C39.1@3351.88,4464.32
  Bottom Layer w20: v4(3275.12,4498.88) v4(3351.88,4498.88)
pads on no net: FID1.1 FID2.1 FID3.1 FID4.1 FID5.1 FID6.1 H1.1 H2.1 H3.1 H4.1 H5.1 H6.1 H7.1 H8.1 H9.0 H10.0 H11.0 H12.0 H13.0 H14.0 H15.0 H16.0 LBL1.0 Q3.9@856.83,3071.92 Q3.9@856.83,3142 Q3.9@913.91,3071.92 Q3.9@913.91,3105.39 Q3.9@913.91,3142 Q3.9@971,3071.92 Q3.9@971,3142 Q4.9@3931.88,3172.34 Q4.9@3931.88,3229.43 Q4.9@3931.88,3286.51 Q4.9@3965.35,3229.43 Q4.9@4001.96,3172.34 Q4.9@4001.96,3229.43 Q4.9@4001.96,3286.51 Q5.0 Q6.0 U1.6 U1.10 U1.20 U1.21 U1.40 U2.7 U3.7 U4.4A U4.4B U4.8A U4.8B U4.9A U4.9B U4.9C U4.9D U4.10A U4.10B U4.14A U4.14B U6.7@337.69,4372.39 U6.7@373.13,4372.39 U7.9@2433,4517.35 U9.7@1644.05,4538.54 U9.7@1644.05,4573.98 U10.4 U11.11@3214.88,4581.62 U11.11@3214.88,4601.31 U11.11@3250.31,4591.46 U11.11@3299.92,4591.46 U11.11@3335.35,4581.62 U11.11@3335.35,4601.31 U12. U12.8@3568.51,3627.95 U12.8@3568.51,3647.64 U12.8@3568.51,3667.32 U12.8@3644.45,3647.64 U12.12 U12.13 U12.18@3842.88,3647.64 U12.18@3918.9,3627.95 U12.18@3918.9,3647.64 U12.18@3918.9,3667.32 U13.0 U15.7@3741.71,4524.37 U15.7@3741.71,4559.8 U17.8 U17.9 U17.10 U17.11@4353.07,3779.11 U17.11@4393.62,3779.11 U17.11@4434.17,3779.11 U19.1 U19.2 U19.7 U19.8 U19.13 U19.14 U19.15 U19.16 U19.19 U19.20 U19.21 U19.25 U19.26 U19.27 U19.29@2342,1902 U20.9@564.57,3736.26 U20.9@600,3736.26 U21.1 U22.9@506,1161.28 U22.9@506,1196.72 U23.7@505,1040.57 U23.7@505,1076 U24.1@1611.8,989.98 U24.2@1611.8,1045.1 U24.8@1611.8,1192.74 U24.9@1611.8,1247.86 U24.10@1553.73,1247.86 U24.11@1495.66,1247.86 U24.12@1495.66,1192.74 U24.18@1495.66,1045.1 U24.19@1495.66,989.98 U24.20@1553.73,989.98 U24.21@1580.31,1045.5 U24.21@1580.31,1091.95 U24.22@1580.31,1145.89 U24.22@1580.31,1192.35 U24.23@1527.16,1145.89 U24.23@1527.16,1192.35 U24.24@1527.16,1045.5 U24.24@1527.16,1091.95 U25.2 U25.3 U25.15 U25.16 U25.26 U27.21@4166.99,594.82 U27.21@4166.99,636.15 U27.21@4166.99,677.49 U27.21@4211.09,594.82 U27.21@4211.09,636.15 U27.21@4211.09,677.49 U29.9@1349.44,331.4 U29.9@1384.87,331.4 U32.10 U32.31A U35.1 U39.15@1861,3039 U44.1

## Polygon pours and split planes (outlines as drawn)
NetC188_1 on Top Layer "vo" (solid, pour order 410): 764,79 541,79 528,92 528,97 528,160 528,170 532,174 536,178 754,178 760,178 766,172 766,82 763,79
5V_H on Top Layer "gn" (solid, pour order 402): 22 vertices, not listed, extent 796,4028 1128,4239
PM_2.5V_OUT on Top Layer "gn" (solid, pour order 394): 27 vertices, not listed, extent 843,2429 2572,2644
GND on Top Layer "gn" (solid, pour order 382): 26 vertices, not listed, extent 2109,4160.45 2602,4785
NetC7_1 on Top Layer "gn" (solid, pour order 380): 18 vertices, not listed, extent 1895.74,4526.25 2055.81,4716.43
NetC7_1 on Top Layer "gn" (solid, pour order 378): 18 vertices, not listed, extent 2610,4525.83 2770.07,4716
NetL7_2 on Top Layer "gn" (solid, pour order 350): 20 vertices, not listed, extent 2801,3434 3066,3626
NetC50_1 on Top Layer "gn" (solid, pour order 348): 3092,3560 3092,3622 3061,3653 3061,3695 3061,3699 3064,3702 3168,3702 3202,3668 3202,3490.45 3195.06,3483.51 3097.49,3483.51 3092,3489
NetC52_1 on Top Layer "gn" (solid, pour order 346): 2754,3545 2754,3699 2819,3764 2842,3764 2846,3760 2846,3702 2827,3683 2827,3521 2822,3516 2770,3516 2754,3532
NetC28_1 on Top Layer "gn" (solid, pour order 334): 22 vertices, not listed, extent 123.35,3512 519,3720
GND_5V on Top Layer "gn" (solid, remove dead copper, pour order 302): 2698,1034 2698,1144 2709,1155 2717,1163 2885,1163 2916.97,1163 2928.97,1151 2928.97,945.97 2920,937 2708,937 2698,947
PMIC_3V3_EN on Top Layer "gn" (solid, remove dead copper, pour order 300): 18 vertices, not listed, extent 2809,1146 3180,1246
PMIC_1V1_EN on Top Layer "gn" (solid, remove dead copper, pour order 298): 3075.76,858.26 3157.26,858.26 3180,881 3197,898 3197,935 3197,943 3193,947 3165,947 3145,927 3142,924 3068,924 2814,924 2808.94,918.94 2808.94,865.06 2815.74,858.26
SVC_5V on Top Layer "gn" (solid, remove dead copper, pour order 296): 21 vertices, not listed, extent 4510,4347 4763,4819
NetC171_1 on Top Layer "gn" (solid, remove dead copper, pour order 294): 4710,4090 4710,4137 4720,4147 4720,4259 4723,4262 4760,4262 4763,4259 4763,4148.52 4778.98,4132.54 4828.46,4132.54 4835,4126 4835,3954 4824,3943 4721,3943 4710,3954
NetL12_1 on Top Layer "gn" (solid, remove dead copper, pour order 292): 3086,1041 2959,1041 2951,1033 2948,1030 2948,983 2948,978.15 2953.72,972.43 3129.43,972.43 3139,982 3139,1036 3134,1041
GND_5V on Top Layer "gn" (solid, remove dead copper, pour order 290): 20 vertices, not listed, extent 3057,109 3304,690
NetC177_1 on Top Layer "gn" (solid, remove dead copper, pour order 288): 17 vertices, not listed, extent 3155,109 3289,482
NetC56_1 on Top Layer "gn" (solid, remove dead copper, pour order 284): 18 vertices, not listed, extent 4179.36,3981 4385,4161.39
NetC150_1 on Top Layer "gn" (solid, remove dead copper, pour order 276): 4334,4426 4334,4337 4311,4314 4260,4314 4250,4304 4250,4205 4254,4201 4380.15,4201 4383,4203.85 4387,4207.85 4387,4423 4387,4445 4385,4447 4336,4447 4334,4445
VOUT2 on Top Layer "gn" (solid, remove dead copper, pour order 272): 17 vertices, not listed, extent 4607.14,842 4865.02,1590
NetD2_1 on Top Layer "gn" (solid, remove dead copper, pour order 266): 4548,750 4548,706 4561,693 4563,691 4563,647 4563,553 4569,547 4850,547 4858,555 4874.86,571.86 4874.86,684.14 4874.86,770.76 4865.02,780.6 4554.6,780.6 4548,774
GND_5V on Top Layer "gn" (solid, remove dead copper, pour order 198): 19 vertices, not listed, extent 4064,975 4618,1590
GND_5V on Top Layer "gn" (solid, remove dead copper, pour order 196): 19 vertices, not listed, extent 3666,411 3991,663
PMIC_IN on Top Layer "gn" (solid, remove dead copper, pour order 194): 17 vertices, not listed, extent 3630,659 4054,892
VOUT1 on Top Layer "gn" (solid, remove dead copper, pour order 192): 4170,1536 4170,1279 4231,1218 4425,1218 4443,1236 4451,1244 4451,1530 4451,1575 4436,1590 4181,1590 4170,1579
NetD1_1 on Top Layer "gn" (solid, remove dead copper, pour order 190): 3747,1487 3747,940 3785,902 3858,902 3897,902 3907,912 3907,1039 3907,1543 3892,1558 3764,1558 3747,1541
NetC145_1 on Top Layer "gn" (solid, remove dead copper, pour order 186): 1883,2272 1795,2272 1783,2260 1783,2009 1791,2001 1883,2001 1894,2012 1894,2247 1894,2261
NetC145_1 on Top Layer "gn" (solid, pour order 184): 2206,1822 2021,1822 2013,1814 2013,1725 2023,1715 2176,1715 2180,1719 2180,1769 2189,1778 2251.37,1778 2255.39,1782.02 2255.39,1817.26 2250.64,1822 2207,1822
PM_3.6V_OUT on Top Layer "gn" (solid, remove dead copper, pour order 182): 21 vertices, not listed, extent 1805,1379 2255.39,1976
GND_5V on Top Layer "gn" (solid, remove dead copper, pour order 180): 72 vertices, not listed, extent 2063.46,1510 2923,2097
3.6I_3P3V on Top Layer "gn" (solid, remove dead copper, pour order 178): 20 vertices, not listed, extent 2426.65,1673 2803,1822
3.6I_1P8V on Top Layer "gn" (solid, remove dead copper, pour order 176): 21 vertices, not listed, extent 2428.61,1932 2800,2105
NetU25_17 on Top Layer "gn" (solid, pour order 170): 17 vertices, not listed, extent 1130,2097 1336,2390
GND_5V on Top Layer "gn" (solid, remove dead copper, pour order 168): 58 vertices, not listed, extent 67,1561 1553,2348
PM_2.5V_OUT on Top Layer "n" (solid, remove dead copper, pour order 166): 28 vertices, not listed, extent 67,2088 1575,2539
NetC101_1 on Top Layer "n" (solid, remove dead copper, pour order 164): 29 vertices, not listed, extent 414,1626 1326,1955
GND_5V on Top Layer "n" (solid, remove dead copper, pour order 162): 33 vertices, not listed, extent 967.88,206 1896,525
VCC_1.8V_2A on Top Layer "n" (solid, remove dead copper, pour order 158): 22 vertices, not listed, extent 1387,35 1902,287
NetC131_1 on Top Layer "n" (solid, remove dead copper, pour order 156): 17 vertices, not listed, extent 967.88,357 1364,523
GND_5V on Top Layer "n" (solid, remove dead copper, pour order 154): 78 vertices, not listed, extent 1114.18,837 2541,1319
PM_3.6V_OUT on Top Layer "n" (solid, remove dead copper, pour order 152): 39 vertices, not listed, extent 1599,837 2646,1425
NetC69_1 on Top Layer "n" (solid, remove dead copper, pour order 150): 18 vertices, not listed, extent 1119,1023.45 1550.78,1362
GND_5V on Top Layer "n" (solid, remove dead copper, pour order 148): 52 vertices, not listed, extent 86,845 945,1321
5V_EFUSE_OUT on Top Layer "n" (solid, pour order 146): 23 vertices, not listed, extent 532,1002 958,1157
NetC67_1 on Top Layer "n" (solid, remove dead copper, pour order 144): 304,1165 243,1226 113,1226 102,1226 92,1216 86,1210 86,1138 86,1120 92,1114 473,1114 480,1121 480,1165
GND on Top Layer "n" (solid, remove dead copper, pour order 136): 29 vertices, not listed, extent 1793,2759 2681,3292
NetC163_1 on Top Layer "n" (solid, remove dead copper, pour order 132): 24 vertices, not listed, extent 2286,2833 2837,3111
NetC162_2 on Top Layer "n" (solid, remove dead copper, pour order 130): 25 vertices, not listed, extent 1947.61,2909 2253,3191.37
NetC161_1 on Top Layer "n" (solid, remove dead copper, pour order 128): 1947.61,3111.44 1947.61,3284.61 1955,3292 2069,3292 2075,3286 2075,3215 2071,3211 2036,3211 2026,3201 2026,3093 2013,3080 1953.46,3080 1947.61,3085.85
GND on Top Layer "n" (solid, remove dead copper, pour order 126): 1164,3235 1164,3305 1171,3312 1309,3312 1318,3303 1318,3145 1308,3135 1179,3135 1176,3138 1176,3219 1164,3231
GND on Top Layer "n" (solid, remove dead copper, pour order 124): 19 vertices, not listed, extent 84,2765 1051,3217
NetC127_1 on Top Layer "n" (solid, remove dead copper, pour order 122): 19 vertices, not listed, extent 84,3168 1145,3381
GND on Top Layer "n" (solid, remove dead copper, pour order 118): 31 vertices, not listed, extent 3129,2759 4841,3222
NetC139_1 on Top Layer "n" (solid, remove dead copper, pour order 114): 24 vertices, not listed, extent 4006,3010 4843,3396.64
VTT_DDR on Top Layer "n" (solid, remove dead copper, pour order 70): 3386,4424 3498,4424 3504,4418 3504,4174 3495,4165 3390,4165 3382,4173 3382,4420
GND on Top Layer "n" (solid, remove dead copper, pour order 68): 39 vertices, not listed, extent 3053,3417 3453,3876
NetC53_1 on Top Layer "n" (solid, remove dead copper, pour order 66): 3240,3923 3247,3930 3327,3930 3338,3919 3338,3733 3306,3701 3306,3655 3296,3645 3238,3645 3234,3649 3234,3686 3240,3692
1.8V on Top Layer "n" (solid, remove dead copper, pour order 46): 2845.07,4537.83 2845.07,4557.83 2856.07,4568.83 2860.07,4572.83 2860.07,4672.83 2860.07,4847.07 2867.83,4854.83 2963.07,4854.83 2970.07,4847.83 2970.07,4764.83 2970.07,4533.83 2961.07,4524.83 2848.07,4524.83 2845.07,4527.83
GND on Top Layer "n" (solid, remove dead copper, pour order 42): 42 vertices, not listed, extent 2623.07,4336.83 2882.07,4854
AGND on Top Layer "n" (solid, remove dead copper, pour order 36): 23 vertices, not listed, extent 1508.67,3465.67 2012.67,3648.67
PH on Top Layer "n" (solid, remove dead copper, pour order 32): 1601.67,3831.67 1601.67,3659.67 1597.67,3655.67 1511.67,3655.67 1507.67,3659.67 1507.67,3817.67 1527.67,3837.67 1596.67,3837.67 1601.67,3832.67
GND on Top Layer "n" (solid, remove dead copper, pour order 30): 50 vertices, not listed, extent 1434.67,3686.67 2260.67,4832.67
5V on Top Layer "n" (solid, remove dead copper, pour order 26): 1946.67,3657.67 2278.67,3657.67 2292,3671 2292,3829 2279.33,3841.67 2211.67,3841.67 1943.01,3841.67 1933.43,3851.25 1894.06,3851.25 1894.06,3663.27 1899.67,3657.67
NetC1_1 on Top Layer "n" (solid, remove dead copper, pour order 24): 30 vertices, not listed, extent 1673.67,3859.12 1858.67,4832.67
NetC17_2 on Top Layer "n" (solid, remove dead copper, pour order 12): 1062,4248 929,4248 926,4251 926,4293 929,4296 965,4296 969,4300 969,4360 973,4364 1017,4364 1066,4315 1066,4281 1066,4251 1063,4248
GND on Top Layer "n" (solid, remove dead copper, pour order 10): 19 vertices, not listed, extent 1020,4127 1375,4468
GND on Top Layer "n" (solid, remove dead copper, pour order 8): 41 vertices, not listed, extent 81,4127 965,4468
NetC20_1 on Top Layer "n" (solid, remove dead copper, pour order 6): 17 vertices, not listed, extent 1035,4462 1296,4604
NetC20_1 on Top Layer "n" (solid, remove dead copper, pour order 4): 29 vertices, not listed, extent 591,4433.08 947,4706
NetC18_1 on Top Layer "n" (solid, remove dead copper, pour order 2): 20 vertices, not listed, extent 80,4339 619.38,4576
NetC27_1 on Top Layer "n" (solid, remove dead copper, pour order 18): 19 vertices, not listed, extent 152,3771.65 774,4105
GND on Top Layer "n" (solid, remove dead copper, pour order 20): 18 vertices, not listed, extent 543,3718 713,3851
3.3V on Top Layer "n" (solid, remove dead copper, pour order 48): 2130.81,4538.25 2130.81,4558.25 2141.81,4569.25 2145.81,4573.25 2145.81,4673.25 2145.81,4852.25 2157.81,4864.25 2239.81,4864.25 2248.81,4855.25 2255.81,4848.25 2255.81,4765.25 2255.81,4534.25 2246.81,4525.25 2133.81,4525.25 2130.81,4528.25
GND on Top Layer "n" (solid, remove dead copper, pour order 58): 44 vertices, not listed, extent 1913.5,4328.45 2176.5,4865.25
GND on Top Layer "n" (solid, remove dead copper, pour order 62): 17 vertices, not listed, extent 3028.85,4449.12 3411.77,4624
1.2V_CPM on Top Layer "n" (solid, remove dead copper, pour order 72): 17 vertices, not listed, extent 2907,3794 3046,4063
GND on Top Layer "n" (solid, remove dead copper, pour order 74): 18 vertices, not listed, extent 2852,3603 2972,3932
NetC61_1 on Top Layer "n" (solid, remove dead copper, pour order 76): 2628,3418 2628,3394 2643,3379 2723,3299 3025,3299 3034,3308 3034,3400 3025,3409 2846,3409 2701,3409 2684,3426 2681,3429 2650,3429 2631,3429 2628,3426
1.8V_CPM on Top Layer "n" (solid, remove dead copper, pour order 78): 20 vertices, not listed, extent 2308,3491 2596,3621
GND on Top Layer "n" (solid, remove dead copper, pour order 82): 28 vertices, not listed, extent 2308,3361 2781,3669
NetJ3_1 on Top Layer "n" (solid, pour order 84): 3770,4687 3770,4800 3770,4825 3779,4834 3782,4837 3832,4837 3891.34,4837 3899.34,4829 3899.34,4483.34 3893,4477 3775,4477 3770,4482
12VOUT on Top Layer "n" (solid, remove dead copper, pour order 86): 24 vertices, not listed, extent 3378,3600 3721,4109
GND on Top Layer "n" (solid, remove dead copper, pour order 92): 49 vertices, not listed, extent 3536,3476 3930.71,4837
NetTP16_1 on Top Layer "n" (solid, remove dead copper, pour order 96): 19 vertices, not listed, extent 3531,3346 3778.15,3588
NetC58_1 on Top Layer "n" (solid, remove dead copper, pour order 98): 17 vertices, not listed, extent 4178,3817 4403,3957
NetC60_1 on Top Layer "n" (solid, remove dead copper, pour order 100): 18 vertices, not listed, extent 4307,3449 4637,3731
GND on Top Layer "n" (solid, remove dead copper, pour order 102): 23 vertices, not listed, extent 4322,3580 4545,4167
